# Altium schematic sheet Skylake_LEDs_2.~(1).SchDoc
size 431 x 279 mm; Date: Not shown in title block; ApprovedBy: Not shown in title block; CheckedBy: Not shown in title block; Author: Not shown in title block; CompanyName: Not shown in title block; Engineer: Not shown in title block; Organization: Not shown in title block; Address1: Not shown in title block; Address2: Not shown in title block; Address3: Not shown in title block; Address4: Not shown in title block; DocumentNumber: 1; Revision: Use project parameter SCH_Rev; SheetNumber: 6; SheetTotal: 9; PageSetup: Record=PageOptions|CenterHorizontal=True|CenterVertical=True|PrintScale=1.00|XCorrection=1.00|YCorrection=1.00|PrintKind=0|BorderSize=5000000|LeftOffset=0|BottomOffset=0|Orientation=2|PaperLength=1000|PaperWidth=1000|Scale=100|PaperSource=15|PrintQuality=600|MediaType=1|DitherType=10|PaperKind=Letter|PrintScaleMode=1
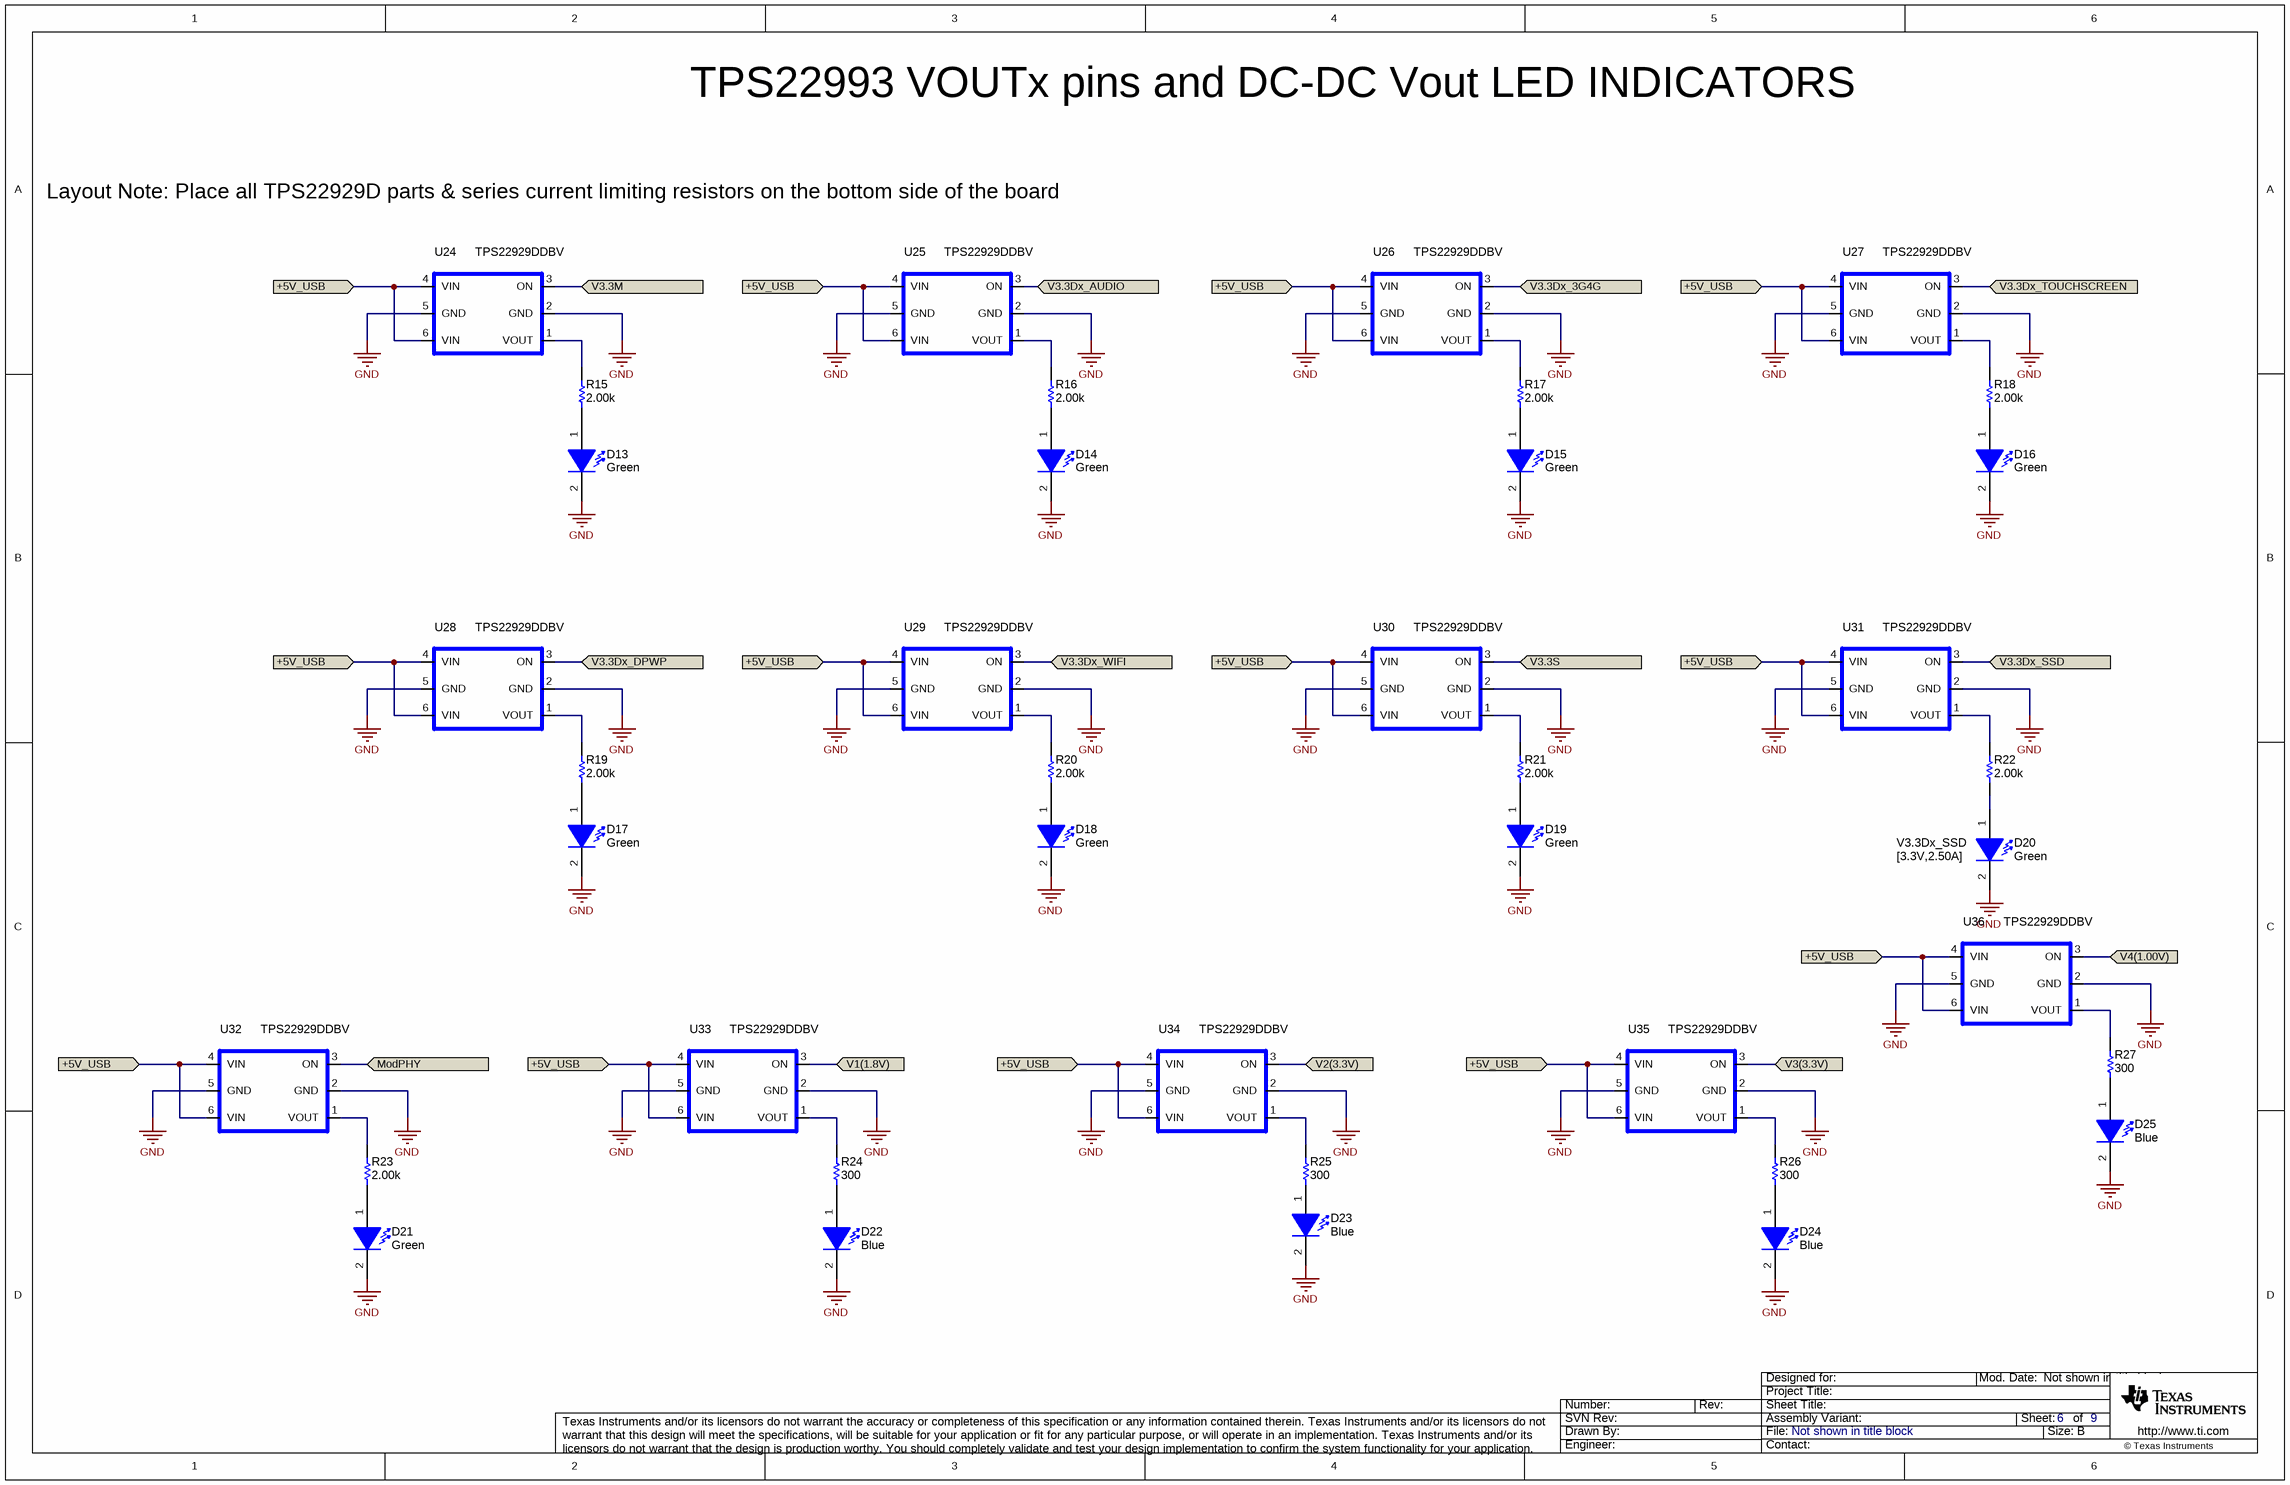
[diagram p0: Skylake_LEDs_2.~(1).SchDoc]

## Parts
D13  value Green  [LED_SML]  (hidden comment: SML312ECTT86)
D14  value Green  [LED_SML]  (hidden comment: SML312ECTT86)
D15  value Green  [LED_SML]  (hidden comment: SML312ECTT86)
D16  value Green  [LED_SML]  (hidden comment: SML312ECTT86)
D17  value Green  [LED_SML]  (hidden comment: SML312ECTT86)
D18  value Green  [LED_SML]  (hidden comment: SML312ECTT86)
D19  value Green  [LED_SML]  (hidden comment: SML312ECTT86)
D20  value Green  [LED_SML]  (hidden comment: SML312ECTT86)
D21  value Green  [LED_SML]  (hidden comment: SML312ECTT86)
D22  value Blue  [LED_SML]  (hidden comment: SML312BCTT86)
D23  value Blue  [LED_SML]  (hidden comment: SML312BCTT86)
D24  value Blue  [LED_SML]  (hidden comment: SML312BCTT86)
D25  value Blue  [LED_SML]  (hidden comment: SML312BCTT86)
R15  value 2.00k  [0603]  (hidden comment: CRCW06032K00FKEA)
R16  value 2.00k  [0603]  (hidden comment: CRCW06032K00FKEA)
R17  value 2.00k  [0603]  (hidden comment: CRCW06032K00FKEA)
R18  value 2.00k  [0603]  (hidden comment: CRCW06032K00FKEA)
R19  value 2.00k  [0603]  (hidden comment: CRCW06032K00FKEA)
R20  value 2.00k  [0603]  (hidden comment: CRCW06032K00FKEA)
R21  value 2.00k  [0603]  (hidden comment: CRCW06032K00FKEA)
R22  value 2.00k  [0603]  (hidden comment: CRCW06032K00FKEA)
R23  value 2.00k  [0603]  (hidden comment: CRCW06032K00FKEA)
R24  value 300  [0603]  (hidden comment: CRCW0603300RJNEA)
R25  value 300  [0603]  (hidden comment: CRCW0603300RJNEA)
R26  value 300  [0603]  (hidden comment: CRCW0603300RJNEA)
R27  value 300  [0603]  (hidden comment: CRCW0603300RJNEA)
U24  TPS22929DDBV  [DBV-6]
U25  TPS22929DDBV  [DBV-6]
U26  TPS22929DDBV  [DBV-6]
U27  TPS22929DDBV  [DBV-6]
U28  TPS22929DDBV  [DBV-6]
U29  TPS22929DDBV  [DBV-6]
U30  TPS22929DDBV  [DBV-6]
U31  TPS22929DDBV  [DBV-6]
U32  TPS22929DDBV  [DBV-6]
U33  TPS22929DDBV  [DBV-6]
U34  TPS22929DDBV  [DBV-6]
U35  TPS22929DDBV  [DBV-6]
U36  TPS22929DDBV  [DBV-6]

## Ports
+5V_USB (in), ModPHY (in), V1(1.8V) (in), V2(3.3V) (in), V3(3.3V) (in), V3.3Dx_3G4G (in), V3.3Dx_AUDIO (in), V3.3Dx_DPWP (in), V3.3Dx_SSD (in), V3.3Dx_TOUCHSCREEN (in), V3.3Dx_WIFI (in), V3.3M (in), V3.3S (in), V4(1.00V) (in)

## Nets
GND: D13.2(K) D14.2(K) D15.2(K) D16.2(K) D17.2(K) D18.2(K) D19.2(K) D20.2(K) D21.2(K) D22.2(K) D23.2(K) D24.2(K) D25.2(K) U24.2(GND) U24.5(GND) U25.2(GND) U25.5(GND) U26.2(GND) U26.5(GND) U27.2(GND) U27.5(GND) U28.2(GND) U28.5(GND) U29.2(GND) U29.5(GND) U30.2(GND) U30.5(GND) U31.2(GND) U31.5(GND) U32.2(GND) U32.5(GND) U33.2(GND) U33.5(GND) U34.2(GND) U34.5(GND) U35.2(GND) U35.5(GND) U36.2(GND) U36.5(GND)
+5V_USB: U24.4(VIN) U24.6(VIN) U25.4(VIN) U25.6(VIN) U26.4(VIN) U26.6(VIN) U27.4(VIN) U27.6(VIN) U28.4(VIN) U28.6(VIN) U29.4(VIN) U29.6(VIN) U30.4(VIN) U30.6(VIN) U31.4(VIN) U31.6(VIN) U32.4(VIN) U32.6(VIN) U33.4(VIN) U33.6(VIN) U34.4(VIN) U34.6(VIN) U35.4(VIN) U35.6(VIN) U36.4(VIN) U36.6(VIN) ; port +5V_USB
ModPHY: U32.3(ON) ; port ModPHY
V1(1.8V): U33.3(ON) ; port V1(1.8V)
V2(3.3V): U34.3(ON) ; port V2(3.3V)
V3(3.3V): U35.3(ON) ; port V3(3.3V)
V3.3Dx_3G4G: U26.3(ON) ; port V3.3Dx_3G4G
V3.3Dx_AUDIO: U25.3(ON) ; port V3.3Dx_AUDIO
V3.3Dx_DPWP: U28.3(ON) ; port V3.3Dx_DPWP
V3.3Dx_SSD: U31.3(ON) ; port V3.3Dx_SSD
V3.3Dx_TOUCHSCREEN: U27.3(ON) ; port V3.3Dx_TOUCHSCREEN
V3.3Dx_WIFI: U29.3(ON) ; port V3.3Dx_WIFI
V3.3M: U24.3(ON) ; port V3.3M
V3.3S: U30.3(ON) ; port V3.3S
V4(1.00V): U36.3(ON) ; port V4(1.00V)
NetD13_1: D13.1(A) R15.1
NetD14_1: D14.1(A) R16.1
NetD15_1: D15.1(A) R17.1
NetD16_1: D16.1(A) R18.1
NetD17_1: D17.1(A) R19.1
NetD18_1: D18.1(A) R20.1
NetD19_1: D19.1(A) R21.1
NetD20_1: D20.1(A) R22.1
NetD21_1: D21.1(A) R23.1
NetD22_1: D22.1(A) R24.1
NetD23_1: D23.1(A) R25.1
NetD24_1: D24.1(A) R26.1
NetD25_1: D25.1(A) R27.1
NetR15_2: R15.2 U24.1(VOUT)
NetR16_2: R16.2 U25.1(VOUT)
NetR17_2: R17.2 U26.1(VOUT)
NetR18_2: R18.2 U27.1(VOUT)
NetR19_2: R19.2 U28.1(VOUT)
NetR20_2: R20.2 U29.1(VOUT)
NetR21_2: R21.2 U30.1(VOUT)
NetR22_2: R22.2 U31.1(VOUT)
NetR23_2: R23.2 U32.1(VOUT)
NetR24_2: R24.2 U33.1(VOUT)
NetR25_2: R25.2 U34.1(VOUT)
NetR26_2: R26.2 U35.1(VOUT)
NetR27_2: R27.2 U36.1(VOUT)

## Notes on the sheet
- TPS22993 VOUTx pins and DC-DC Vout LED INDICATORS
- Layout Note: Place all TPS22929D parts & series current limiting resistors on the bottom side of the board
- (near D20) V3.3Dx_SSD
  [3.3V,2.50A]

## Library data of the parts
D13-D21 = SML312WBCW1: LED, Green, SMD; Manufacturer: Rohm; Type: AlInGaP; ColorTemperature: 8000K; Vf_V: 3; Value2: 3V; Io_A: 0.005; Value1: W; U/M: EA
D22-D25 = SML312WBCW1: LED, Blue, SMD; Manufacturer: Rohm; Type: AlInGaP; ColorTemperature: 8000K; Vf_V: 3; Value2: 3V; Io_A: 0.005; Value1: W; U/M: EA
R15-R23 = CRCW06032K00FKEA: RES, 2.00k ohm, 1%, 0.1W, 0603; Manufacturer: Vishay-Dale; CompType: Resistor; Res_ohm: 2000; Value_Code: 2k00; Tolerance_%: 1; Power_W: 0.1; VDC_V: 75; TempCo: 100 ppm/C; EIA_Code: E96; U/M: EA
R24-R27 = CRCW0603300RJNEA: RES, 300 ohm, 5%, 0.1W, 0603; Manufacturer: Vishay-Dale; CompType: Resistor; Value_Code: 300R; Tolerance_%: 5; Power_W: 0.1; VDC_V: 75; TempCo: 200 ppm/C; EIA_Code: E24; U/M: EA
U24-U36 = TPS2292XDBV: IC, LOW INPUT VOLTAGE LOAD SWITCH  WITH CONTROLLED TURN-ON; Manufacturer: TI; Alternate Manufacturer: None; Area: 18.50 mm; Value: TPS22929DBV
